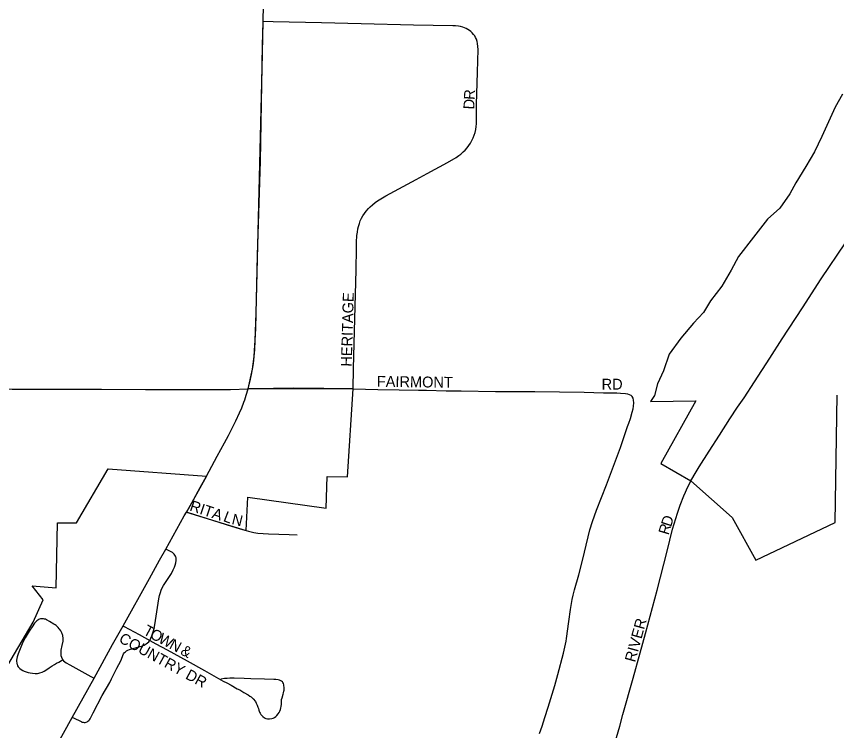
# Model space of a CAD drawing. Extents: x 1772825 to 1773716, y 1138558 to 1139032.
# Drawn here: x 1773356.3 to 1773370.59, y 1138901.21 to 1138913.65 of the extents above; entities that cross this region are included whole.
import ezdxf

# ---------------------------------------------------------------- set-up
doc = ezdxf.new("R2010")
doc.units = 0
for name, color, linetype in [('GM_X_City_Street', 7, 'Continuous'), ('GM_X_City_Street_Text', 7, 'Continuous'), ('GM_X_Corporation', 7, 'Continuous'), ('GM_X_State_Route', 7, 'Continuous'), ('GM_X_Township_Road', 7, 'Continuous')]:
    doc.layers.add(name, color=color, linetype=linetype)

msp = doc.modelspace()

# ---------------------------------------------------------------- linework, layer by layer
at = {"layer": 'GM_X_City_Street'}
for points in [[(1773362.167, 1138907.165), (1773362.173, 1138907.521), (1773362.196, 1138908.383), (1773362.218, 1138909.24), (1773362.224, 1138909.613), (1773362.228, 1138909.723), (1773362.235, 1138909.835), (1773362.242, 1138909.897), (1773362.251, 1138909.951), (1773362.261, 1138909.993), (1773362.278, 1138910.049), (1773362.293, 1138910.092), (1773362.314, 1138910.139), (1773362.338, 1138910.179), (1773362.365, 1138910.221), (1773362.395, 1138910.26), (1773362.433, 1138910.307), (1773362.464, 1138910.338), (1773362.503, 1138910.374), (1773362.549, 1138910.412), (1773362.594, 1138910.443), (1773362.74, 1138910.526), (1773363.263, 1138910.813), (1773363.46, 1138910.919), (1773363.809, 1138911.11), (1773363.961, 1138911.197), (1773364.009, 1138911.229), (1773364.044, 1138911.256), (1773364.084, 1138911.292), (1773364.118, 1138911.326), (1773364.154, 1138911.367), (1773364.183, 1138911.404), (1773364.212, 1138911.447), (1773364.237, 1138911.491), (1773364.259, 1138911.539), (1773364.277, 1138911.584), (1773364.292, 1138911.633), (1773364.303, 1138911.683), (1773364.31, 1138911.734), (1773364.315, 1138911.784), (1773364.318, 1138912.121), (1773364.333, 1138912.684), (1773364.343, 1138913.078), (1773364.34, 1138913.131), (1773364.334, 1138913.18), (1773364.327, 1138913.214), (1773364.314, 1138913.255), (1773364.301, 1138913.284), (1773364.285, 1138913.314), (1773364.265, 1138913.341), (1773364.244, 1138913.366), (1773364.22, 1138913.389), (1773364.195, 1138913.409), (1773364.166, 1138913.427), (1773364.139, 1138913.443), (1773364.107, 1138913.457), (1773364.078, 1138913.466), (1773364.038, 1138913.476), (1773364.002, 1138913.482), (1773363.952, 1138913.487), (1773363.902, 1138913.49), (1773363.217, 1138913.503), (1773362.31, 1138913.526), (1773361.615, 1138913.542), (1773360.773, 1138913.561), (1773360.6, 1138913.565)], [(1773360.34, 1138907.163), (1773360.783, 1138907.179), (1773361.132, 1138907.181), (1773361.655, 1138907.176), (1773362.167, 1138907.165)], [(1773362.167, 1138907.165), (1773362.597, 1138907.155), (1773362.971, 1138907.149), (1773363.306, 1138907.144), (1773363.443, 1138907.142), (1773363.791, 1138907.133), (1773364.052, 1138907.13), (1773364.649, 1138907.122), (1773365.022, 1138907.122), (1773365.333, 1138907.12), (1773366.192, 1138907.106), (1773366.527, 1138907.099), (1773366.577, 1138907.098), (1773366.689, 1138907.096), (1773366.763, 1138907.094), (1773366.825, 1138907.093), (1773366.909, 1138907.085), (1773366.944, 1138907.08), (1773366.977, 1138907.069), (1773367.005, 1138907.053), (1773367.027, 1138907.03)], [(1773365.413, 1138901.161), (1773365.458, 1138901.289), (1773365.505, 1138901.443), (1773365.564, 1138901.62), (1773365.634, 1138901.845), (1773365.68, 1138901.999), (1773365.734, 1138902.191), (1773365.833, 1138902.562), (1773365.877, 1138902.769), (1773365.885, 1138902.819), (1773365.925, 1138903.11), (1773365.955, 1138903.319), (1773365.98, 1138903.494), (1773365.999, 1138903.573), (1773366.023, 1138903.662), (1773366.097, 1138903.925), (1773366.16, 1138904.178), (1773366.259, 1138904.59), (1773366.292, 1138904.711), (1773366.336, 1138904.854), (1773366.407, 1138905.054), (1773366.578, 1138905.495), (1773366.723, 1138905.865), (1773366.826, 1138906.145), (1773366.891, 1138906.333), (1773366.947, 1138906.51), (1773366.969, 1138906.569), (1773366.996, 1138906.651), (1773367.026, 1138906.757), (1773367.044, 1138906.817), (1773367.053, 1138906.865), (1773367.058, 1138906.923), (1773367.052, 1138906.968), (1773367.043, 1138907.001), (1773367.027, 1138907.03)], [(1773367.959, 1138905.366), (1773367.976, 1138905.405), (1773368.052, 1138905.563), (1773368.144, 1138905.72)], [(1773366.67, 1138900.793), (1773366.811, 1138901.29), (1773366.868, 1138901.492), (1773367.048, 1138902.125), (1773367.17, 1138902.566), (1773367.263, 1138902.904), (1773367.462, 1138903.661), (1773367.635, 1138904.335), (1773367.733, 1138904.722), (1773367.815, 1138904.997), (1773367.864, 1138905.138), (1773367.93, 1138905.3), (1773367.959, 1138905.366)], [(1773359.265, 1138905.019), (1773359.297, 1138905.009), (1773360.049, 1138904.773), (1773360.202, 1138904.725), (1773360.302, 1138904.697)], [(1773360.302, 1138904.697), (1773360.348, 1138904.685), (1773360.436, 1138904.664), (1773360.51, 1138904.652), (1773360.601, 1138904.643), (1773360.694, 1138904.637), (1773361.055, 1138904.627), (1773361.192, 1138904.622)], [(1773358.629, 1138902.781), (1773358.663, 1138902.861), (1773358.687, 1138902.931), (1773358.701, 1138902.993), (1773358.712, 1138903.052), (1773358.748, 1138903.279), (1773358.783, 1138903.506), (1773358.796, 1138903.565), (1773358.81, 1138903.617), (1773358.824, 1138903.659), (1773358.842, 1138903.7), (1773358.863, 1138903.737), (1773358.888, 1138903.776), (1773358.956, 1138903.878), (1773359.002, 1138903.95), (1773359.036, 1138904.014), (1773359.054, 1138904.057), (1773359.067, 1138904.095), (1773359.078, 1138904.135), (1773359.086, 1138904.175), (1773359.087, 1138904.198), (1773359.084, 1138904.219), (1773359.08, 1138904.233), (1773359.074, 1138904.25), (1773359.063, 1138904.268), (1773359.051, 1138904.283), (1773359.035, 1138904.301), (1773359.019, 1138904.314), (1773358.903, 1138904.374)], [(1773356.744, 1138903.161), (1773356.739, 1138903.161), (1773356.722, 1138903.158), (1773356.704, 1138903.154), (1773356.688, 1138903.146), (1773356.674, 1138903.137), (1773356.659, 1138903.126), (1773356.645, 1138903.112), (1773356.62, 1138903.085), (1773356.605, 1138903.065), (1773356.588, 1138903.039), (1773356.526, 1138902.945), (1773356.455, 1138902.829), (1773356.416, 1138902.752), (1773356.391, 1138902.696), (1773356.355, 1138902.605), (1773356.334, 1138902.548), (1773356.318, 1138902.499), (1773356.311, 1138902.466), (1773356.307, 1138902.438), (1773356.306, 1138902.418), (1773356.308, 1138902.391), (1773356.311, 1138902.381)], [(1773357.114, 1138902.444), (1773357.113, 1138902.444), (1773357.103, 1138902.459), (1773357.092, 1138902.486), (1773357.085, 1138902.512), (1773357.081, 1138902.561), (1773357.085, 1138902.611), (1773357.102, 1138902.697), (1773357.116, 1138902.77), (1773357.118, 1138902.819), (1773357.112, 1138902.868), (1773357.095, 1138902.914), (1773357.077, 1138902.948), (1773357.06, 1138902.971), (1773357.048, 1138902.987), (1773357.03, 1138903.007), (1773357.014, 1138903.023), (1773356.994, 1138903.041), (1773356.976, 1138903.055), (1773356.955, 1138903.069), (1773356.881, 1138903.113), (1773356.84, 1138903.136), (1773356.825, 1138903.143), (1773356.808, 1138903.151), (1773356.795, 1138903.155), (1773356.777, 1138903.16), (1773356.759, 1138903.161), (1773356.744, 1138903.161)], [(1773358.161, 1138903.038), (1773358.181, 1138903.027), (1773358.442, 1138902.884), (1773358.629, 1138902.781)], [(1773357.276, 1138901.442), (1773357.297, 1138901.432), (1773357.428, 1138901.368), (1773357.444, 1138901.361), (1773357.463, 1138901.356), (1773357.481, 1138901.354), (1773357.5, 1138901.355), (1773357.517, 1138901.357), (1773357.535, 1138901.365), (1773357.548, 1138901.374), (1773357.564, 1138901.388), (1773357.574, 1138901.401), (1773357.586, 1138901.419), (1773357.639, 1138901.522), (1773357.799, 1138901.822), (1773357.928, 1138902.051), (1773357.961, 1138902.116), (1773358.053, 1138902.298), (1773358.119, 1138902.429), (1773358.17, 1138902.548), (1773358.186, 1138902.571), (1773358.202, 1138902.584), (1773358.221, 1138902.6), (1773358.246, 1138902.614), (1773358.274, 1138902.626), (1773358.352, 1138902.649), (1773358.415, 1138902.665), (1773358.5, 1138902.69), (1773358.529, 1138902.703), (1773358.562, 1138902.724), (1773358.608, 1138902.759), (1773358.629, 1138902.781)], [(1773358.629, 1138902.781), (1773358.731, 1138902.725), (1773358.928, 1138902.619), (1773359.275, 1138902.428), (1773359.58, 1138902.26), (1773359.904, 1138902.076), (1773359.97, 1138902.042), (1773360.045, 1138902.001), (1773360.149, 1138901.942), (1773360.192, 1138901.921), (1773360.266, 1138901.876), (1773360.341, 1138901.833), (1773360.371, 1138901.813), (1773360.391, 1138901.799), (1773360.427, 1138901.766), (1773360.465, 1138901.719), (1773360.48, 1138901.692), (1773360.496, 1138901.653), (1773360.509, 1138901.621), (1773360.519, 1138901.595), (1773360.528, 1138901.57), (1773360.533, 1138901.552), (1773360.539, 1138901.534), (1773360.55, 1138901.514), (1773360.562, 1138901.492), (1773360.575, 1138901.474), (1773360.593, 1138901.456), (1773360.622, 1138901.435), (1773360.648, 1138901.424), (1773360.678, 1138901.417), (1773360.712, 1138901.416), (1773360.753, 1138901.422), (1773360.776, 1138901.43), (1773360.799, 1138901.441), (1773360.819, 1138901.455), (1773360.84, 1138901.475), (1773360.864, 1138901.503), (1773360.88, 1138901.527), (1773360.89, 1138901.553), (1773360.901, 1138901.581), (1773360.907, 1138901.608), (1773360.914, 1138901.634), (1773360.919, 1138901.674), (1773360.918, 1138901.701), (1773360.92, 1138901.722), (1773360.923, 1138901.751), (1773360.931, 1138901.785), (1773360.951, 1138901.846), (1773360.957, 1138901.87), (1773360.961, 1138901.896), (1773360.964, 1138901.916), (1773360.965, 1138901.943), (1773360.965, 1138901.967), (1773360.963, 1138901.991), (1773360.96, 1138902.011), (1773360.954, 1138902.03), (1773360.945, 1138902.05), (1773360.936, 1138902.061), (1773360.921, 1138902.074), (1773360.906, 1138902.081), (1773360.886, 1138902.09), (1773360.865, 1138902.096), (1773360.823, 1138902.102), (1773360.785, 1138902.103), (1773360.626, 1138902.108), (1773360.386, 1138902.116), (1773360.27, 1138902.12), (1773360.094, 1138902.124), (1773360.019, 1138902.125), (1773359.973, 1138902.122), (1773359.926, 1138902.117), (1773359.864, 1138902.107)], [(1773356.311, 1138902.381), (1773356.314, 1138902.368), (1773356.324, 1138902.341), (1773356.335, 1138902.323), (1773356.346, 1138902.309), (1773356.362, 1138902.294), (1773356.387, 1138902.276), (1773356.412, 1138902.261), (1773356.438, 1138902.248), (1773356.472, 1138902.235), (1773356.505, 1138902.223), (1773356.541, 1138902.217), (1773356.586, 1138902.211), (1773356.629, 1138902.208), (1773356.653, 1138902.208), (1773356.671, 1138902.209), (1773356.691, 1138902.211), (1773356.713, 1138902.216), (1773356.75, 1138902.229), (1773356.788, 1138902.248), (1773356.831, 1138902.276), (1773356.876, 1138902.307), (1773356.928, 1138902.343), (1773356.965, 1138902.366), (1773357.004, 1138902.388), (1773357.04, 1138902.406), (1773357.089, 1138902.431), (1773357.114, 1138902.444), (1773357.125, 1138902.43), (1773357.145, 1138902.411), (1773357.167, 1138902.393), (1773357.231, 1138902.355), (1773357.599, 1138902.157), (1773357.655, 1138902.127)]]:
    msp.add_lwpolyline(points, dxfattribs=at)
at = {"layer": 'GM_X_Corporation'}
for points in [[(1773355.878, 1138901.897), (1773356.594, 1138903.099), (1773356.77, 1138903.488), (1773356.58, 1138903.733), (1773356.998, 1138903.698), (1773357.021, 1138904.832), (1773357.351, 1138904.833), (1773357.903, 1138905.775), (1773359.612, 1138905.647), (1773359.265, 1138905.019), (1773360.302, 1138904.697), (1773360.335, 1138905.276), (1773361.701, 1138905.089), (1773361.716, 1138905.641), (1773362.068, 1138905.631), (1773362.166, 1138907.165), (1773360.34, 1138907.163), (1773360.414, 1138907.507), (1773360.444, 1138907.73), (1773360.458, 1138907.925), (1773360.462, 1138908.006), (1773360.478, 1138908.485), (1773360.581, 1138912.742), (1773360.6, 1138913.565), (1773360.631, 1138914.991)], [(1773370.693, 1138912.3), (1773370.563, 1138912.072), (1773370.421, 1138911.754), (1773370.33, 1138911.56), (1773370.203, 1138911.295), (1773370.055, 1138911.039), (1773369.878, 1138910.757), (1773369.773, 1138910.564), (1773369.6, 1138910.311), (1773369.384, 1138910.119), (1773369.144, 1138909.81), (1773368.882, 1138909.472), (1773368.753, 1138909.234), (1773368.592, 1138908.952), (1773368.395, 1138908.697), (1773368.27, 1138908.493), (1773368.097, 1138908.308), (1773367.876, 1138908.05), (1773367.671, 1138907.771), (1773367.572, 1138907.479), (1773367.469, 1138907.252), (1773367.419, 1138907.048), (1773367.349, 1138906.945), (1773368.136, 1138906.957), (1773367.527, 1138905.864), (1773368.052, 1138905.563), (1773368.771, 1138904.927), (1773369.184, 1138904.182), (1773370.565, 1138904.836), (1773370.597, 1138907.057)]]:
    msp.add_lwpolyline(points, dxfattribs=at)
at = {"layer": 'GM_X_State_Route'}
for points in [[(1773360.34, 1138907.163), (1773360.381, 1138907.337), (1773360.396, 1138907.417), (1773360.414, 1138907.507), (1773360.431, 1138907.61), (1773360.444, 1138907.73), (1773360.455, 1138907.843), (1773360.462, 1138908.006), (1773360.471, 1138908.215), (1773360.504, 1138909.494), (1773360.552, 1138911.133), (1773360.588, 1138913.146), (1773360.6, 1138913.565), (1773360.615, 1138914.139), (1773360.631, 1138914.991)], [(1773360.279, 1138906.975), (1773360.306, 1138907.055), (1773360.34, 1138907.163)], [(1773359.612, 1138905.647), (1773359.8, 1138905.992), (1773359.926, 1138906.224), (1773359.997, 1138906.353), (1773360.071, 1138906.501), (1773360.125, 1138906.606), (1773360.191, 1138906.75), (1773360.227, 1138906.836), (1773360.265, 1138906.934), (1773360.279, 1138906.975)], [(1773359.265, 1138905.019), (1773359.361, 1138905.178), (1773359.506, 1138905.449), (1773359.612, 1138905.647)], [(1773358.798, 1138904.183), (1773358.903, 1138904.374), (1773359.224, 1138904.951), (1773359.265, 1138905.019)], [(1773356.404, 1138899.868), (1773356.672, 1138900.351), (1773357.276, 1138901.442), (1773357.655, 1138902.127), (1773357.979, 1138902.711), (1773358.161, 1138903.038), (1773358.62, 1138903.862), (1773358.798, 1138904.183)]]:
    msp.add_lwpolyline(points, dxfattribs=at)
at = {"layer": 'GM_X_Township_Road'}
for points in [[(1773368.144, 1138905.72), (1773368.195, 1138905.806), (1773368.367, 1138906.078), (1773368.547, 1138906.36), (1773368.73, 1138906.644), (1773368.863, 1138906.848), (1773368.976, 1138907.01), (1773369.16, 1138907.288), (1773369.425, 1138907.699), (1773369.643, 1138908.037), (1773369.997, 1138908.578), (1773370.32, 1138909.08), (1773370.743, 1138909.708), (1773370.983, 1138910.064), (1773371.565, 1138910.973), (1773371.712, 1138911.207), (1773371.85, 1138911.426), (1773372.125, 1138911.843), (1773372.322, 1138912.142), (1773372.546, 1138912.478)], [(1773350.057, 1138907.175), (1773350.238, 1138907.176), (1773351.207, 1138907.176), (1773352.214, 1138907.174), (1773353.569, 1138907.165), (1773354.737, 1138907.164), (1773356.229, 1138907.162), (1773357.783, 1138907.159), (1773358.553, 1138907.156), (1773359.473, 1138907.155), (1773359.834, 1138907.156), (1773360.033, 1138907.155), (1773360.34, 1138907.163)]]:
    msp.add_lwpolyline(points, dxfattribs=at)

# ---------------------------------------------------------------- texts
at = {"layer": 'GM_X_City_Street_Text'}
for s, height, rotation, p in [('R', 0.189, 86.404, (1773364.283, 1138912.196)), ('D', 0.189, 87.9671, (1773364.277, 1138912.031)), ('HERITAGE', 0.1894, 88.3616, (1773362.143, 1138907.55)), ('FAIRMONT', 0.1894, 359.2145, (1773362.58, 1138907.202)), ('RD', 0.1894, 0, (1773366.496, 1138907.152)), ('RITA', 0.1894, 341.5694, (1773359.307, 1138905.049)), ('L', 0.189, 339.3097, (1773359.893, 1138904.865)), ('N', 0.189, 346.2427, (1773360.041, 1138904.811)), ('D', 0.189, 71.8415, (1773367.704, 1138904.751)), ('R', 0.189, 73.324, (1773367.661, 1138904.609)), ('RIVER', 0.1894, 74.6488, (1773367.078, 1138902.392)), ('T', 0.189, 331.6382, (1773358.496, 1138902.898)), ('O', 0.189, 331.6322, (1773358.613, 1138902.834)), ('COUNTRY DR', 0.1894, 331.2443, (1773358.073, 1138902.762)), ('W', 0.189, 331.6378, (1773358.76, 1138902.755)), ('N', 0.189, 331.6322, (1773358.951, 1138902.652)), ('&', 0.189, 332.8068, (1773359.145, 1138902.547))]:
    msp.add_text(s, height=height, rotation=rotation, dxfattribs=at).set_placement(p)

doc.saveas('drawing.dxf')
